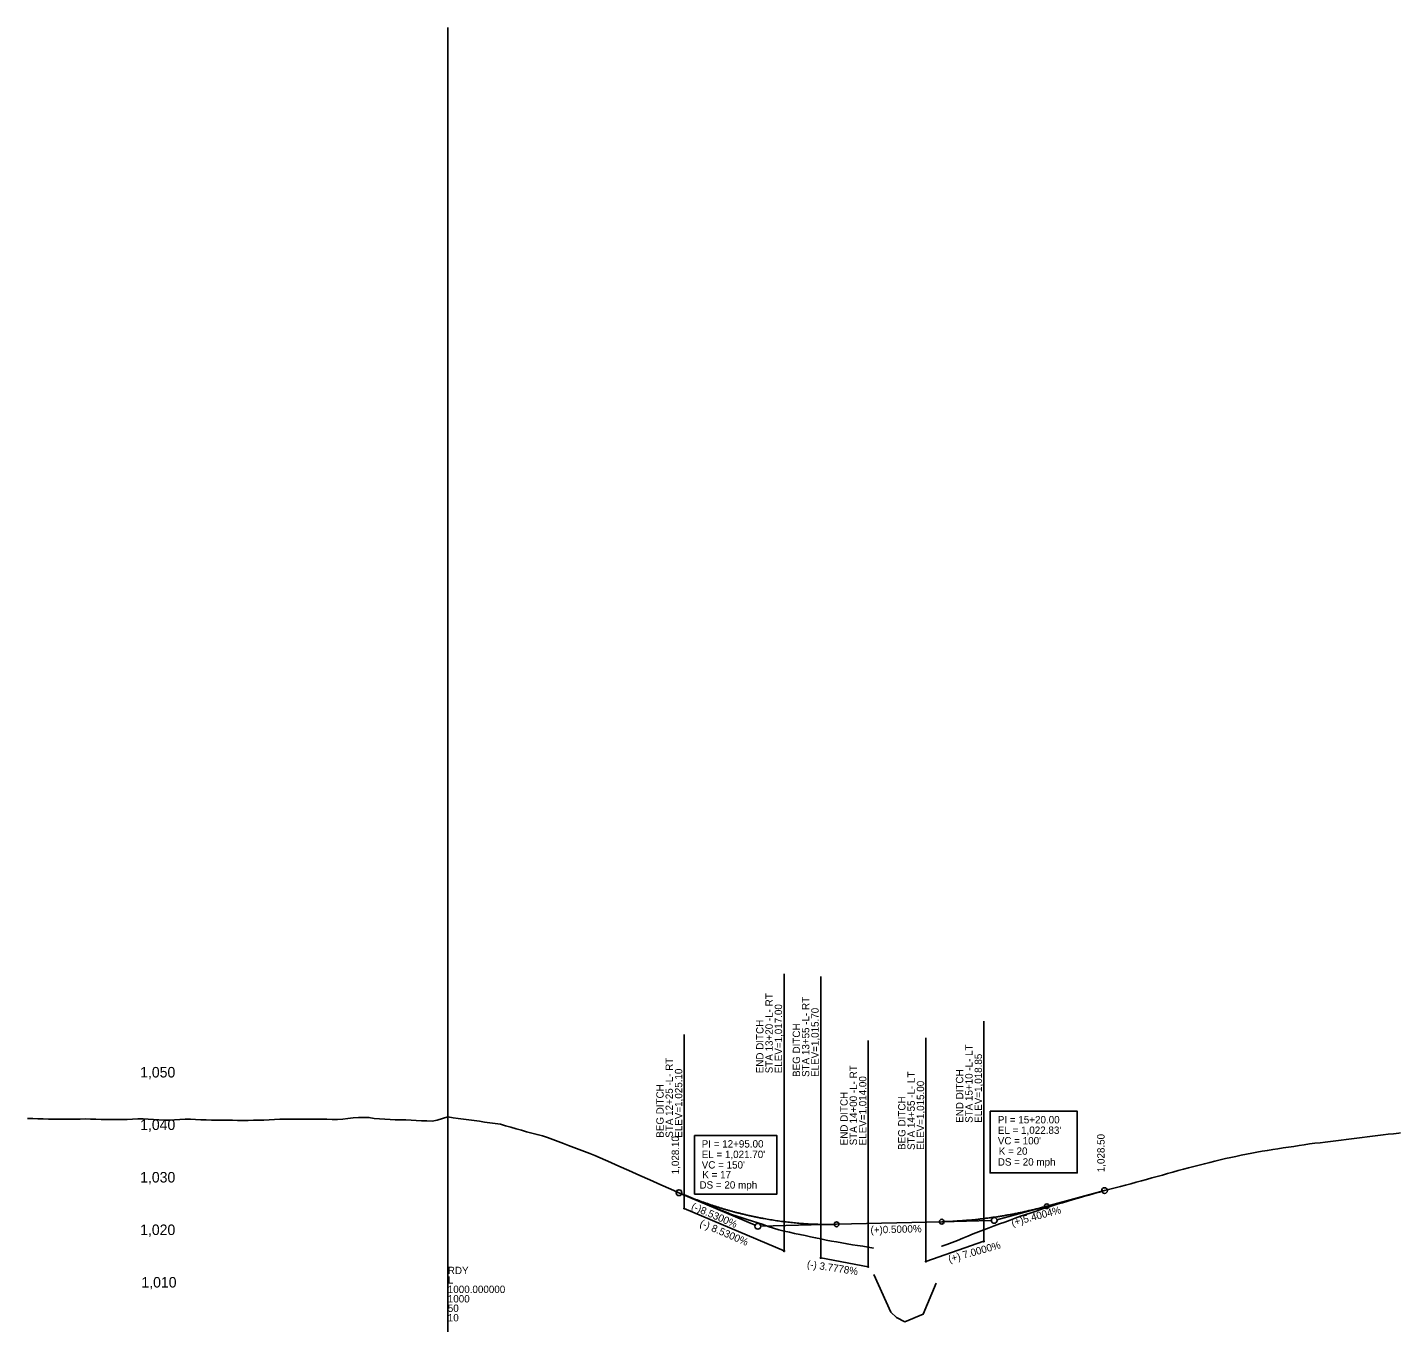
# Model space of a CAD drawing. Extents: x 1427711 to 1429114, y 853103 to 858103.
# Drawn here: x 1427714 to 1429021, y 856869 to 858103 of the extents above; entities that cross this region are included whole.
import ezdxf

# ---------------------------------------------------------------- set-up
doc = ezdxf.new("R2010")
doc.units = 0
for name, color, linetype in [('Exist Profile Cell', 7, 'Continuous'), ('Exist Vertical Profile Ground Line', 7, 'Continuous'), ('Exist Vertical Profile Vertical Axis Label', 7, 'Continuous'), ('Prop Grid Mask', 7, 'Continuous'), ('Prop Vertical Profile Curve Label', 7, 'Continuous'), ('Prop Vertical Profile Ditch Grade Left', 7, 'Continuous'), ('Prop Vertical Profile Ditch Grade Left Label', 7, 'Continuous'), ('Prop Vertical Profile Ditch Grade Right', 7, 'Continuous'), ('Prop Vertical Profile Ditch Grade Right Label', 7, 'Continuous'), ('Prop Vertical Profile Grade', 7, 'Continuous'), ('Prop Vertical Profile Grade Label', 7, 'Continuous'), ('Prop VPI Ditch Grade Left Label', 7, 'Continuous'), ('Prop VPI Ditch Grade Right Label', 7, 'Continuous'), ('Prop VPI Label', 7, 'Continuous')]:
    doc.layers.add(name, color=color, linetype=linetype)

msp = doc.modelspace()

# ---------------------------------------------------------------- linework, layer by layer
at = {"layer": 'Exist Profile Cell'}
msp.add_line((1428114, 856852.6), (1428114, 858102.6), dxfattribs=at)
at = {"layer": 'Exist Vertical Profile Ground Line'}
for points in [[(1427714, 857063.9), (1427719, 857063.7), (1427724, 857063.5), (1427729, 857063.4), (1427734, 857063.2), (1427739, 857063.2), (1427744, 857063.2), (1427749, 857063.1), (1427754, 857063.1), (1427759, 857063.2), (1427764, 857063.2), (1427769, 857063.3), (1427774, 857063.2), (1427779, 857063), (1427784, 857062.8), (1427789, 857062.8), (1427794, 857062.8), (1427799, 857062.8), (1427804, 857062.8), (1427809, 857062.9), (1427814, 857063), (1427819, 857063.3), (1427824, 857063.4), (1427829, 857063.1), (1427834, 857062.8), (1427839, 857062.5), (1427844, 857062.2), (1427849, 857062.3), (1427854, 857062.6), (1427859, 857062.8), (1427864, 857063), (1427869, 857063.1), (1427874, 857062.8), (1427879, 857062.6), (1427884, 857062.5), (1427889, 857062.3), (1427894, 857062.3), (1427899, 857062.2), (1427904, 857062.1), (1427909, 857062), (1427914, 857061.9), (1427919, 857061.9), (1427924, 857061.9), (1427929, 857062), (1427934, 857062.2), (1427939, 857062.3), (1427944, 857062.5), (1427949, 857062.7), (1427954, 857063), (1427959, 857063.1), (1427964, 857063.1), (1427969, 857063.2), (1427974, 857063.2), (1427979, 857063.2), (1427984, 857063.2), (1427989, 857063.2), (1427994, 857063.2), (1427999, 857063.2), (1428004, 857062.9), (1428009, 857062.7), (1428014, 857063.2), (1428019, 857063.7), (1428024, 857064.3), (1428029, 857064.8), (1428034, 857064.7), (1428039, 857064.8), (1428044, 857063.7), (1428049, 857063.4), (1428054, 857063.1), (1428059, 857062.8), (1428064, 857062.6), (1428069, 857062.5), (1428074, 857062.5), (1428079, 857062.3), (1428084, 857061.9), (1428089, 857061.6), (1428094, 857061.4), (1428099, 857061.2), (1428104, 857062.3), (1428109, 857063.7), (1428114, 857065.2), (1428119, 857064.5), (1428124, 857063.8), (1428129, 857063.1), (1428134, 857062.4), (1428139, 857061.8), (1428144, 857061.1), (1428149, 857060.4), (1428154, 857059.7), (1428159, 857059), (1428164, 857058.2), (1428169, 857056.8), (1428174, 857055.4), (1428179, 857054), (1428184, 857052.6), (1428189, 857051.2), (1428194, 857049.8), (1428199, 857048.4), (1428204, 857047.1), (1428209, 857045.7), (1428214, 857043.9)], [(1428714, 856988), (1428719, 856989.4), (1428724, 856990.9), (1428729, 856992.3), (1428734, 856993.7), (1428739, 856995.1), (1428744, 856996.4), (1428749, 856997.7), (1428754, 856998.9), (1428759, 857000.3), (1428764, 857001.6), (1428769, 857003), (1428774, 857004.3), (1428779, 857005.7), (1428784, 857007.1), (1428789, 857008.5), (1428794, 857009.9), (1428799, 857011.3), (1428804, 857012.7), (1428809, 857014.1), (1428814, 857015.4), (1428819, 857016.8), (1428824, 857018.1), (1428829, 857019.4), (1428834, 857020.7), (1428839, 857021.9), (1428844, 857023.2), (1428849, 857024.4), (1428854, 857025.5), (1428859, 857026.6), (1428864, 857027.7), (1428869, 857028.8), (1428874, 857029.7), (1428879, 857030.7), (1428884, 857031.6), (1428889, 857032.5), (1428894, 857033.4), (1428899, 857034.2), (1428904, 857035), (1428909, 857035.8), (1428914, 857036.5), (1428919, 857037.2), (1428924, 857038), (1428929, 857038.7), (1428934, 857039.5), (1428939, 857040.1), (1428944, 857040.7), (1428949, 857041.3), (1428954, 857042), (1428959, 857042.6), (1428964, 857043.2), (1428969, 857043.8), (1428974, 857044.5), (1428979, 857045.1), (1428984, 857045.7), (1428989, 857046.3), (1428994, 857046.9), (1428999, 857047.5), (1429004, 857048.1), (1429009, 857048.7), (1429014, 857049.3), (1429019, 857049.9), (1429020.6, 857050)], [(1428214, 857043.9), (1428219, 857042), (1428224, 857040), (1428229, 857038.1), (1428234, 857036.1), (1428239, 857034.2), (1428244, 857032.2), (1428249, 857030.3), (1428254, 857028.4), (1428259, 857026.2), (1428264, 857024), (1428269, 857021.8), (1428274, 857019.6), (1428279, 857017.4), (1428284, 857015.2), (1428289, 857013), (1428294, 857010.8), (1428299, 857008.6), (1428304, 857006.4), (1428309, 857004.2), (1428314, 857001.9), (1428319, 856999.7), (1428324, 856997.5), (1428329, 856995.3), (1428334, 856993.1), (1428339, 856990.8), (1428344, 856988.7), (1428349, 856986.6), (1428354, 856984.6), (1428359, 856982.6), (1428364, 856980.6), (1428369, 856978.5), (1428374, 856976.5), (1428379, 856974.5), (1428384, 856972.4), (1428389, 856970.8), (1428394, 856969.2), (1428399, 856967.5), (1428404, 856965.9), (1428409, 856964.3), (1428414, 856962.7), (1428419, 856961), (1428424, 856959.4), (1428429, 856957.8), (1428434, 856956.6), (1428439, 856955.5), (1428444, 856954.4), (1428449, 856953.4), (1428454, 856952.3), (1428459, 856951.2), (1428464, 856950.2), (1428469, 856949.1), (1428474, 856948), (1428479, 856947.1), (1428484, 856946.2), (1428489, 856945.3), (1428494, 856944.4), (1428499, 856943.6), (1428504, 856942.7), (1428509, 856942.1), (1428514, 856941.2), (1428519, 856940.4), (1428519, 856940.3)], [(1428583.9, 856942), (1428584, 856942.1), (1428589, 856943.8), (1428594, 856945.6), (1428599, 856947.6), (1428604, 856949.7), (1428609, 856951.8), (1428614, 856953.8), (1428619, 856955.8), (1428624, 856957.8), (1428629, 856959.6), (1428634, 856961.5), (1428639, 856963.3), (1428644, 856965.1), (1428649, 856967), (1428654, 856968.8), (1428659, 856970.6), (1428664, 856972.3), (1428669, 856973.9), (1428674, 856975.6), (1428679, 856977.3), (1428684, 856979), (1428689, 856980.6), (1428694, 856982.1), (1428699, 856983.6), (1428704, 856985), (1428709, 856986.5), (1428714, 856988)], [(1428519.4, 856915.3), (1428535.5, 856879.5), (1428541.1, 856874.3), (1428549, 856870.2), (1428566.4, 856877.3), (1428578.7, 856907.1)]]:
    msp.add_lwpolyline(points, dxfattribs=at)
at = {"layer": 'Prop Grid Mask'}
for points in [[(1428630.1, 857070.7), (1428712.9, 857070.7), (1428712.9, 857012), (1428630.1, 857012)], [(1428348.9, 857047.4), (1428427.2, 857047.4), (1428427.2, 856991.8), (1428348.9, 856991.8)]]:
    msp.add_lwpolyline(points, close=True, dxfattribs=at)
at = {"layer": 'Prop Vertical Profile Curve Label'}
for centre in [(1428684, 856980.2), (1428584, 856965.5), (1428484, 856963)]:
    msp.add_circle(centre, 2.25, dxfattribs=at)
at = {"layer": 'Prop Vertical Profile Ditch Grade Left'}
msp.add_line((1428569, 856927.6), (1428624, 856946.8), dxfattribs=at)
at = {"layer": 'Prop Vertical Profile Ditch Grade Right'}
for p, q in [((1428339, 856978.1), (1428434, 856937.6)), ((1428469, 856931.1), (1428514, 856922.6))]:
    msp.add_line(p, q, dxfattribs=at)
at = {"layer": 'Prop Vertical Profile Grade'}
for p, q in [((1428684, 856980.2), (1428739, 856995.1)), ((1428484, 856963), (1428584, 856965.5))]:
    msp.add_line(p, q, dxfattribs=at)
for points in [[(1428334, 856993.1), (1428337, 856991.8), (1428340, 856990.6), (1428343, 856989.4), (1428346, 856988.2), (1428349, 856987), (1428352, 856985.9), (1428355, 856984.8), (1428358, 856983.7), (1428361, 856982.7), (1428364, 856981.6), (1428367, 856980.6), (1428370, 856979.7), (1428373, 856978.7), (1428376, 856977.8), (1428379, 856976.9), (1428382, 856976.1), (1428385, 856975.2), (1428388, 856974.4), (1428391, 856973.7), (1428394, 856972.9), (1428397, 856972.2), (1428400, 856971.5), (1428403, 856970.8), (1428406, 856970.2), (1428409, 856969.6), (1428412, 856969), (1428415, 856968.4), (1428418, 856967.9), (1428421, 856967.4), (1428424, 856966.9), (1428427, 856966.4), (1428430, 856966), (1428433, 856965.6), (1428436, 856965.2), (1428439, 856964.9), (1428442, 856964.6), (1428445, 856964.3), (1428448, 856964), (1428451, 856963.8), (1428454, 856963.6), (1428457, 856963.4), (1428460, 856963.2), (1428463, 856963.1), (1428466, 856963), (1428469, 856962.9), (1428472, 856962.9), (1428475, 856962.9), (1428478, 856962.9), (1428481, 856962.9), (1428484, 856963)], [(1428584, 856965.5), (1428586, 856965.5), (1428588, 856965.6), (1428590, 856965.7), (1428592, 856965.7), (1428594, 856965.8), (1428596, 856965.9), (1428598, 856966.1), (1428600, 856966.2), (1428602, 856966.3), (1428604, 856966.5), (1428606, 856966.6), (1428608, 856966.8), (1428610, 856966.9), (1428612, 856967.1), (1428614, 856967.3), (1428616, 856967.5), (1428618, 856967.7), (1428620, 856968), (1428622, 856968.2), (1428624, 856968.4), (1428626, 856968.7), (1428628, 856968.9), (1428630, 856969.2), (1428632, 856969.5), (1428634, 856969.8), (1428636, 856970.1), (1428638, 856970.4), (1428640, 856970.7), (1428642, 856971), (1428644, 856971.4), (1428646, 856971.7), (1428648, 856972.1), (1428650, 856972.4), (1428652, 856972.8), (1428654, 856973.2), (1428656, 856973.6), (1428658, 856974), (1428660, 856974.4), (1428662, 856974.9), (1428664, 856975.3), (1428666, 856975.8), (1428668, 856976.2), (1428670, 856976.7), (1428672, 856977.1), (1428674, 856977.6), (1428676, 856978.1), (1428678, 856978.6), (1428680, 856979.2), (1428682, 856979.7), (1428684, 856980.2)]]:
    msp.add_spline(points, degree=3, dxfattribs=at)
at = {"layer": 'Prop VPI Ditch Grade Left Label'}
for p, q in [((1428624, 856946.8), (1428624, 857156.3)), ((1428569, 856927.6), (1428569, 857140.6))]:
    msp.add_line(p, q, dxfattribs=at)
for centre in [(1428624, 856946.8), (1428569, 856927.6)]:
    msp.add_circle(centre, 0.5, dxfattribs=at)
at = {"layer": 'Prop VPI Ditch Grade Right Label'}
for p, q in [((1428434, 856937.6), (1428434, 857201.5)), ((1428469, 856931.1), (1428469, 857199.1)), ((1428339, 856978.1), (1428339, 857143.8)), ((1428514, 856922.6), (1428514, 857137.9))]:
    msp.add_line(p, q, dxfattribs=at)
for centre in [(1428339, 856978.1), (1428434, 856937.6), (1428469, 856931.1), (1428514, 856922.6)]:
    msp.add_circle(centre, 0.5, dxfattribs=at)
at = {"layer": 'Prop VPI Label'}
for p, q in [((1428334, 856993.1), (1428406.5, 856962.2)), ((1428684, 856980.2), (1428636.6, 856967.4)), ((1428584, 856965.5), (1428631.2, 856966.6)), ((1428484, 856963), (1428411.7, 856961.2))]:
    msp.add_line(p, q, dxfattribs=at)
for centre in [(1428334, 856993.1), (1428739, 856995.1), (1428634, 856966.7), (1428409, 856961.1)]:
    msp.add_circle(centre, 2.75, dxfattribs=at)

# ---------------------------------------------------------------- texts
at = {"layer": 'Exist Profile Cell'}
for s, p in [('RDY', (1428114, 856915.6)), ('1000.000000', (1428114, 856897.6)), ('L', (1428114, 856906.6)), ('1000', (1428114, 856888.6)), ('50', (1428114, 856879.6)), ('10', (1428114, 856870.6))]:
    msp.add_text(s, height=7, dxfattribs=at).set_placement(p)
at = {"layer": 'Exist Vertical Profile Vertical Axis Label'}
for s, p in [('1,050', (1427821.2, 857102.8)), ('1,040', (1427821.2, 857052.8)), ('1,030', (1427821.2, 857002.8)), ('1,020', (1427821.2, 856952.8)), ('1,010', (1427822.4, 856902.8))]:
    msp.add_text(s, height=10, dxfattribs=at).set_placement(p)
at = {"layer": 'Prop Vertical Profile Curve Label'}
for s, p in [("VC = 100'", (1428637.4, 857039.1)), ('K = 20', (1428638.3, 857029.2)), ("VC = 150'", (1428355.6, 857016.1)), ('DS = 20 mph', (1428637.4, 857018.9)), ('K = 17', (1428356.2, 857006.8)), ('DS = 20 mph', (1428353.5, 856997))]:
    msp.add_text(s, height=7, dxfattribs=at).set_placement(p)
at = {"layer": 'Prop Vertical Profile Ditch Grade Left Label'}
msp.add_text('(+) 7.0000%', height=7, rotation=15.6422, dxfattribs=at).set_placement((1428591.3, 856926.4))
at = {"layer": 'Prop Vertical Profile Ditch Grade Right Label'}
for s, rotation, p in [('(-) 8.5300%', 336.9018, (1428353.1, 856961.5)), ('(-) 3.7778%', 351.407, (1428455.4, 856921.9))]:
    msp.add_text(s, height=7, rotation=rotation, dxfattribs=at).set_placement(p)
at = {"layer": 'Prop Vertical Profile Grade Label'}
for s, rotation, p in [('(-)8.5300%', 336.9018, (1428345, 856977.5)), ('(+)5.4004%', 15.1106, (1428651.2, 856961)), ('(+)0.5000%', 1.4321, (1428516.3, 856954.2))]:
    msp.add_text(s, height=7, rotation=rotation, dxfattribs=at).set_placement(p)
at = {"layer": 'Prop VPI Ditch Grade Left Label'}
for s, p in [('STA 15+10 -L- LT', (1428613.4, 857059.6)), ('ELEV=1,018.85', (1428622.3, 857059.6)), ('STA 14+55 -L- LT', (1428558.4, 857033.8)), ('ELEV=1,015.00', (1428567.3, 857033.8)), ('END DITCH', (1428604.5, 857059.6)), ('BEG DITCH', (1428549.5, 857033.8))]:
    msp.add_text(s, height=7, rotation=90, dxfattribs=at).set_placement(p)
at = {"layer": 'Prop VPI Ditch Grade Right Label'}
for s, p in [('STA 13+20 -L- RT', (1428423.2, 857106.8)), ('STA 13+55 -L- RT', (1428458, 857103.3)), ('ELEV=1,017.00', (1428432.1, 857106.8)), ('ELEV=1,015.70', (1428466.9, 857103.3)), ('END DITCH', (1428414.4, 857106.8)), ('BEG DITCH', (1428449.2, 857103.3)), ('STA 12+25 -L- RT', (1428328.2, 857045.4)), ('ELEV=1,025.10', (1428337.1, 857045.4)), ('STA 14+00 -L- RT', (1428503.4, 857038.2)), ('ELEV=1,014.00', (1428512.3, 857038.2)), ('BEG DITCH', (1428319.4, 857045.4)), ('END DITCH', (1428494.5, 857038.2))]:
    msp.add_text(s, height=7, rotation=90, dxfattribs=at).set_placement(p)
at = {"layer": 'Prop VPI Label'}
for s, p in [('PI = 15+20.00', (1428637.4, 857059.1)), ("EL = 1,022.83'", (1428637.4, 857049.1)), ('PI = 12+95.00', (1428355.6, 857036.1)), ("EL = 1,021.70'", (1428355.6, 857026.1))]:
    msp.add_text(s, height=7, dxfattribs=at).set_placement(p)
for s, p in [('1,028.10', (1428334, 857010.6)), ('1,028.50', (1428739, 857012.6))]:
    msp.add_text(s, height=7, rotation=90, dxfattribs=at).set_placement(p)

doc.saveas('drawing.dxf')
